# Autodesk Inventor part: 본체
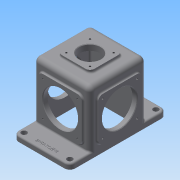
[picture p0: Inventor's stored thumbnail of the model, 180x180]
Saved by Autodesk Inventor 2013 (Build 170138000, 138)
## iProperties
Created: 2018-09
Part Number: 본체
Material: 알루미늄 6061
Document SubType Name: Modeling
Designer: mduedu
Density: 2.71 g/cm^3
Mass: 973.076 g
Surface Area: 1113.23 cm^2
Volume: 359.069 cm^3
Author: mduedu
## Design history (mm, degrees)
sketch "스케치1"
  geometry: L1 (90, 52.5)-(-90, 52.5); L2 (-90, 52.5)-(-90, -52.5); L3 (-90, -52.5)-(90, -52.5); L4 (90, -52.5)-(90, 52.5); L5 (90, 52.5)-(-90, -52.5); L6 (-90, 52.5)-(90, -52.5); 1 further point
  constraints: 12 end point, 2 midpoint, 2 parallel, 1 horizontal, 1 perpendicular
  dimensions: "d0" = 180 distance of L3.end L2.end; "d1" = 105 distance of L2.end L1.end
extrude "돌출1" new body sketch "스케치1" distance "d2" = 10; taper "d3" = 0 deg
sketch "스케치2"
  geometry: L1 (-52.5, -52.5)-(52.5, -52.5); L2 (52.5, -52.5)-(52.5, 52.5); L3 (52.5, 52.5)-(-52.5, 52.5); L4 (-52.5, 52.5)-(-52.5, -52.5); L5 (-52.5, -52.5)-(52.5, 52.5); L6 (52.5, -52.5)-(-52.5, 52.5); 1 further point
  constraints: 12 end point, 2 midpoint, 2 parallel, 1 horizontal, 1 perpendicular
  dimensions: "d4" = 105 distance of L3.end L2.end; "d5" = 105 distance of L2.end L1.end
extrude "돌출2" join sketch "스케치2" distance "d6" = 105; taper "d7" = 0 deg
node "작업 평면1"
sketch "스케치3"
  geometry: L1 (-52.5, 52.5)-(52.5, 52.5) reference; L2 (52.5, 52.5)-(52.5, -52.5) reference; L3 (52.5, -52.5)-(-52.5, -52.5) reference; L4 (-52.5, -52.5)-(-52.5, 52.5) reference; L5 (46.5, 46.5)-(-46.5, 46.5); L6 (-46.5, 46.5)-(-46.5, -46.5); L7 (-46.5, -46.5)-(46.5, -46.5); L8 (46.5, -46.5)-(46.5, 46.5); 1 further point
  constraints: 8 end point, 3 other
  dimensions: "d9" = 6 distance between parallel lines of L5 L1
extrude "돌출3" cut sketch "스케치3" stored distance "d10" = 105; taper "d11" = 0 deg
fillet "모깎기1" dims "d12" = 9
fillet "모깎기2" dims "d13" = 9
fillet "모깎기3" dims "d14" = 3
fillet "모깎기4" dims "d15" = 3
sketch "스케치4"
  geometry: L1 (-30, -30)-(30, -30); L2 (30, -30)-(30, 30); L3 (30, 30)-(-30, 30); L4 (-30, 30)-(-30, -30); L5 (-30, -30)-(30, 30); L6 (30, -30)-(-30, 30); 1 further point
  constraints: 12 end point, 2 midpoint, 2 parallel, 1 horizontal, 1 perpendicular
  dimensions: "d16" = 60 distance of L3.end L2.end; "d17" = 60 distance of L2.end L1.end
extrude "돌출4" join sketch "스케치4" distance "d18" = 5; taper "d19" = 0 deg
fillet "모깎기5" dims "d20" = 8
fillet "모깎기6" dims "d21" = 3
sketch "스케치5"
  geometry: C1 r 20 at (0, 0); 1 further point
  constraints: 1 centre point, 1 coincident
  dimensions: "d22" = 40 diameter of C1
extrude "돌출5" cut sketch "스케치5" stored distance "d23" = 5; taper "d24" = 0 deg
sketch "스케치6"
  geometry: L1 (50, 17.5)-(130, 17.5); L2 (130, 17.5)-(130, 97.5); L3 (130, 97.5)-(50, 97.5); L4 (50, 97.5)-(50, 17.5); L5 (50, 17.5)-(130, 97.5); L6 (130, 17.5)-(50, 97.5); L7 (0, 0)-(180, 0) reference; 4 further points
  constraints: 12 end point, 4 midpoint, 2 parallel, 1 horizontal, 1 perpendicular, 1 vertical alignment
  dimensions: "d25" = 80 distance of L3.end L2.end; "d26" = 80 distance of L2.end L1.end; "d27" = 57.5 distance of point (90, 0) point (90, 57.5)
extrude "돌출6" join sketch "스케치6" distance "d28" = 3; taper "d29" = 0 deg
fillet "모깎기7" dims "d30" = 8
sketch "스케치7"
  geometry: C1 r 32.5 at (90, 57.5); 1 further point
  constraints: 1 centre point, 1 vertical alignment
  dimensions: "d32" = 65 diameter of C1; "d33" = 57.5 distance of C1.centre point (90, 0)
extrude "돌출7" cut sketch "스케치7" stored distance "d34" = 3; taper "d35" = 0 deg
fillet "모깎기9" dims "d36" = 3
sketch "스케치8"
  geometry: L1 (3.5, 7.5)-(83.5, 7.5); L2 (83.5, 7.5)-(83.5, 87.5); L3 (83.5, 87.5)-(3.5, 87.5); L4 (3.5, 87.5)-(3.5, 7.5); L5 (3.5, 7.5)-(83.5, 87.5); L6 (83.5, 7.5)-(3.5, 87.5); L7 (-9, -10)-(96, -10) reference; C1 r 32.5 at (43.5, 47.5); 4 further points
  constraints: 12 end point, 4 midpoint, 2 parallel, 1 centre point, 1 coincident, 1 horizontal, 1 perpendicular, 1 vertical alignment
  dimensions: "d37" = 80 distance of L3.end L2.end; "d38" = 80 distance of L2.end L1.end; "d39" = 57.5 distance from line of point (43.5, 47.5) L7; "d40" = 65 diameter of C1
extrude "돌출8" join sketch "스케치8" distance "d41" = 3; taper "d42" = 0 deg
fillet "모깎기10" dims "d43" = 8
extrude "돌출9" cut sketch "스케치8" stored distance "d44" = 3; taper "d45" = 0 deg
fillet "모깎기11" dims "d46" = 3
sketch "스케치9"
  geometry: L1 (50, 89.5)-(50, 25.5) reference; L2 (58, 17.5)-(122, 17.5) reference; L3 (130, 25.5)-(130, 89.5) reference; L4 (122, 97.5)-(58, 97.5) reference; C1 r 32.5 at (90, 57.5) reference; A1 r 8 centre (58, 89.5) between (58, 97.5) and (50, 89.5) reference; A2 r 8 centre (58, 25.5) between (50, 25.5) and (58, 17.5) reference; A3 r 8 centre (122, 25.5) between (122, 17.5) and (130, 25.5) reference; A4 r 8 centre (122, 89.5) between (130, 89.5) and (122, 97.5) reference; 5 further points
  constraints: 4 coincident
hole "구멍1" sketch "스케치9" at (58, 89.5), (122, 89.5), (122, 25.5), (58, 25.5) diameter "d47" = 3.242; stored, may be unused: countersink angle "d51" = 90 deg, drill point angle "d53" = 118 deg; dims "d48" = 6, "d49" = 4, "d50" = 2, "d52" = 9
sketch "스케치10"
  geometry: L1 (11.5, 7.5)-(75.5, 7.5) reference; L2 (83.5, 15.5)-(83.5, 79.5) reference; L3 (75.5, 87.5)-(11.5, 87.5) reference; L4 (3.5, 79.5)-(3.5, 15.5) reference; C1 r 32.5 at (43.5, 47.5) reference; A1 r 8 centre (11.5, 15.5) between (3.5, 15.5) and (11.5, 7.5) reference; A2 r 8 centre (75.5, 15.5) between (75.5, 7.5) and (83.5, 15.5) reference; A3 r 8 centre (75.5, 79.5) between (83.5, 79.5) and (75.5, 87.5) reference; A4 r 8 centre (11.5, 79.5) between (11.5, 87.5) and (3.5, 79.5) reference; 5 further points
  constraints: 4 coincident
hole "구멍2" sketch "스케치10" at (11.5, 79.5), (75.5, 79.5), (75.5, 15.5), (11.5, 15.5) diameter "d54" = 3.242; stored, may be unused: countersink angle "d58" = 90 deg, drill point angle "d60" = 118 deg; dims "d55" = 6, "d56" = 4, "d57" = 2, "d59" = 9
sketch "스케치11"
  geometry: L1 (22, 30)-(-22, 30) reference; L2 (-30, 22)-(-30, -22) reference; L3 (-22, -30)-(22, -30) reference; L4 (30, -22)-(30, 22) reference; C1 r 20 at (0, 0) reference; A1 r 8 centre (22, 22) between (30, 22) and (22, 30) reference; A2 r 8 centre (-22, 22) between (-22, 30) and (-30, 22) reference; A3 r 8 centre (-22, -22) between (-30, -22) and (-22, -30) reference; A4 r 8 centre (22, -22) between (22, -30) and (30, -22) reference; 5 further points
  constraints: 4 coincident
hole "구멍3" sketch "스케치11" at (-22, 22), (22, 22), (22, -22), (-22, -22) diameter "d61" = 3.242; stored, may be unused: countersink angle "d65" = 90 deg, drill point angle "d67" = 118 deg; dims "d62" = 7, "d63" = 4, "d64" = 2, "d66" = 9
fillet "모깎기12" dims "d68" = 10
sketch "스케치12"
  geometry: L1 (-90, 42.5)-(-90, -42.5) reference; L2 (-80, -52.5)-(-43.5, -52.5) reference; L3 (-52.5, -43.5)-(-52.5, 43.5) reference; L4 (-43.5, 52.5)-(-80, 52.5) reference; A1 r 10 centre (-80, 42.5) between (-80, 52.5) and (-90, 42.5) reference; A2 r 10 centre (-80, -42.5) between (-90, -42.5) and (-80, -52.5) reference; A3 r 9 centre (-43.5, -43.5) between (-52.5, -43.5) and (-43.5, -52.5) reference; A4 r 9 centre (-43.5, 43.5) between (-43.5, 52.5) and (-52.5, 43.5) reference; 3 further points
  constraints: 2 coincident
hole "구멍4" sketch "스케치12" at (-80, 42.5), (-80, -42.5) diameter "d70" = 10; stored, may be unused: countersink angle "d74" = 90 deg, drill point angle "d76" = 118 deg; dims "d71" = 6, "d72" = 4, "d73" = 2, "d75" = 9
fillet "모깎기13" dims "d77" = 3
fillet "모깎기14" dims "d78" = 3
chamfer "모따기1" distance "d79" = 1; stored, may be unused: second distance "d80" = 2, angle "d81" = 45 deg
sketch "스케치13"
  geometry: L1 (90, -42.5)-(90, 42.5) reference; 2 further points
  constraints: 1 horizontal alignment, 1 other
  dimensions: "d82" = 10 distance from line of point (80, 0) L1
feature "엠보싱1" sketch "스케치13" dims "d83" = 0.5, "d84" = 0
node "솔리드1"
mirror "대칭1"
mirror "대칭2"
mirror "대칭3"
node "투영된 루프1"
node "투영된 루프2"
node "투영된 루프3"
node "투영된 루프4"
node "투영된 루프5"
other parameters: "d8" = -6
